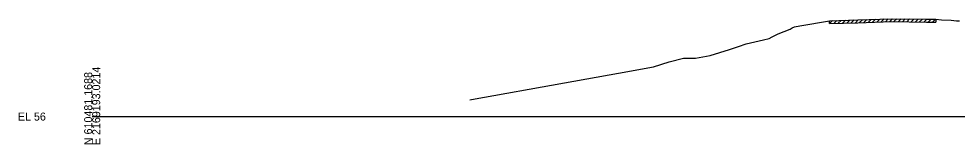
# Model space of a CAD drawing. Extents: x -26 to 6803, y -10 to 19606.
# Drawn here: x 1974.3 to 2302.7, y 10490.3 to 10534.3 of the extents above; entities that cross this region are included whole.
import ezdxf

# ---------------------------------------------------------------- set-up
doc = ezdxf.new("R2010")
doc.units = 0
for name, color, linetype in [('RD_GPK_XS_Cell', 7, 'Continuous'), ('RD_XS_ExGround', 7, 'Continuous'), ('RD_XS_ExPaveRet', 7, 'Continuous')]:
    doc.layers.add(name, color=color, linetype=linetype)

msp = doc.modelspace()

# ---------------------------------------------------------------- linework, layer by layer
at = {"layer": 'RD_GPK_XS_Cell'}
msp.add_line((2000, 10500), (2400, 10500), dxfattribs=at)
at = {"layer": 'RD_XS_ExGround'}
msp.add_lwpolyline([(2132.09, 10505.91), (2132.72, 10506), (2165.22, 10511.83), (2184.15, 10515.24), (2196.44, 10517.47), (2201.9, 10519.19), (2206.91, 10520.47), (2209.54, 10520.49), (2211.04, 10520.45), (2216.24, 10521.37), (2222.94, 10523.44), (2226.88, 10524.83), (2228.08, 10525.22), (2228.82, 10525.43), (2234.91, 10526.83), (2236.81, 10527.34), (2237.89, 10527.89), (2238.34, 10528.17), (2239.59, 10528.76), (2240.02, 10529.01), (2244.23, 10530.6), (2244.88, 10531.06), (2245.75, 10531.45), (2247.53, 10531.76), (2258.01, 10533.56), (2267.83, 10533.89), (2279.66, 10534.26), (2291.93, 10534.11), (2295.12, 10534.07), (2297.21, 10533.93), (2300.55, 10533.73), (2302.4, 10533.55), (2303.47, 10533.49)], dxfattribs=at)
at = {"layer": 'RD_XS_ExPaveRet'}
for p, q in [((2258.01, 10532.56), (2259.05, 10533.6)), ((2258.01, 10532.56), (2258.01, 10533.56)), ((2259.51, 10532.61), (2260.55, 10533.65)), ((2261.01, 10532.66), (2262.05, 10533.7)), ((2262.51, 10532.71), (2263.55, 10533.74)), ((2264.01, 10532.76), (2265.05, 10533.79)), ((2265.51, 10532.81), (2266.55, 10533.84)), ((2267.01, 10532.86), (2268.05, 10533.89)), ((2268.51, 10532.91), (2269.55, 10533.94)), ((2270.01, 10532.96), (2271.05, 10533.99)), ((2271.51, 10533), (2272.55, 10534.04)), ((2273.01, 10533.05), (2274.05, 10534.08)), ((2274.51, 10533.1), (2275.55, 10534.13)), ((2276.01, 10533.15), (2277.05, 10534.18)), ((2277.51, 10533.2), (2278.55, 10534.23)), ((2279.01, 10533.24), (2280.03, 10534.26)), ((2280.51, 10533.25), (2281.5, 10534.24)), ((2282.01, 10533.23), (2283, 10534.22)), ((2283.51, 10533.22), (2284.5, 10534.2)), ((2285.01, 10533.2), (2286, 10534.18)), ((2286.51, 10533.18), (2287.5, 10534.16)), ((2288.01, 10533.16), (2289, 10534.14)), ((2289.51, 10533.14), (2290.5, 10534.12)), ((2291.01, 10533.12), (2292, 10534.11)), ((2292.51, 10533.1), (2293.5, 10534.09)), ((2294.01, 10533.08), (2295, 10534.07)), ((2295.12, 10534.07), (2295.12, 10533.07)), ((2258.01, 10532.56), (2267.83, 10532.89)), ((2258.01, 10532.56), (2258.01, 10532.56)), ((2267.83, 10532.89), (2279.66, 10533.26)), ((2279.66, 10533.26), (2291.93, 10533.11)), ((2291.93, 10533.11), (2295.12, 10533.07))]:
    msp.add_line(p, q, dxfattribs=at)

# ---------------------------------------------------------------- texts
at = {"layer": 'RD_GPK_XS_Cell'}
for s, p in [('E 2169193.0214', (2002.8, 10490)), ('N 610481.1688', (2000, 10490))]:
    msp.add_text(s, height=2.8, rotation=90, dxfattribs=at).set_placement(p)
msp.add_text('EL 56', height=2.8, dxfattribs=at).set_placement((1974, 10498.6))

doc.saveas('drawing.dxf')
